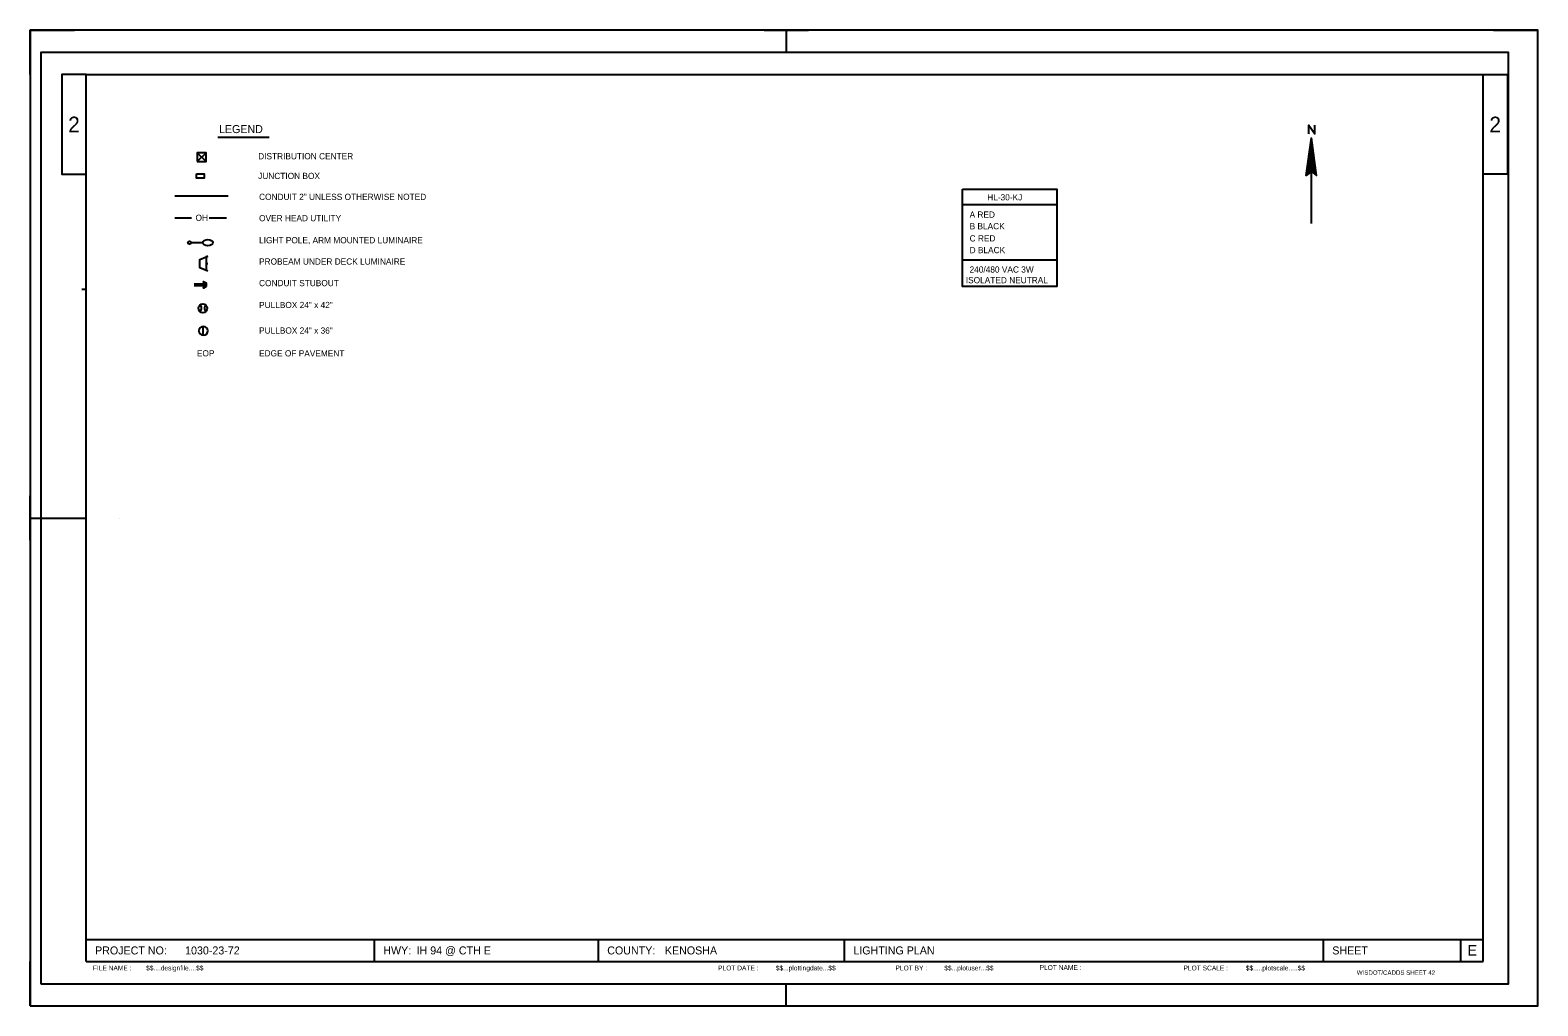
# Model space of a CAD drawing. Extents: x 589059 to 596052, y 152647 to 154942.
# Drawn here: x 589059 to 590759, y 152647 to 153747 of the extents above; entities that cross this region are included whole.
import ezdxf

# ---------------------------------------------------------------- set-up
doc = ezdxf.new("R2010")
doc.units = 0
for name, color, linetype in [('b_center line', 7, 'Continuous'), ('Level 26', 7, 'Continuous'), ('Level 28', 7, 'Continuous'), ('P_DRN_Flow', 7, 'Continuous'), ('P_DRN_SS_UG', 7, 'Continuous')]:
    doc.layers.add(name, color=color, linetype=linetype)

msp = doc.modelspace()

# ---------------------------------------------------------------- linework, layer by layer
at = {"layer": 'b_center line'}
msp.add_line((589270.3, 153625.9), (589328.2, 153625.9), dxfattribs=at)
at = {"layer": 'Level 26'}
for p, q in [((589247, 153608.5), (589257, 153598.5)), ((589247, 153598.5), (589257, 153608.5)), ((590109.8, 153550.2), (590216.2, 153550.2)), ((589240.1, 153507.1), (589253.4, 153507.1)), ((589250.1, 153488.1), (589259.1, 153491.7)), ((589250.1, 153478.5), (589250.1, 153488.1)), ((589259.1, 153475), (589250.1, 153478.5)), ((589257, 153490.9), (589257, 153490.9)), ((589259.1, 153491.7), (589257.1, 153490.9)), ((589257.1, 153490.9), (589257.1, 153475.8)), ((589257.1, 153483.4), (589259.1, 153483.4)), ((590109.8, 153487.7), (590216.2, 153487.7)), ((589253.9, 153402.6), (589253.9, 153412.6)), ((589253.7, 153402.6), (589253.9, 153402.6))]:
    msp.add_line(p, q, dxfattribs=at)
for points in [[(589247, 153598.5), (589257, 153598.5), (589257, 153608.5), (589247, 153608.5)], [(589246.4, 153584.5), (589254.9, 153584.5), (589254.9, 153579.6), (589246.4, 153579.6)], [(590109.8, 153567.2), (590216.2, 153567.2), (590216.2, 153457.5), (590109.8, 153457.5)], [(589257.3, 153457.6), (589254.2, 153455.9), (589255.5, 153459.6), (589254.2, 153463.4), (589257.3, 153461.6)]]:
    msp.add_lwpolyline(points, close=True, dxfattribs=at)
for points in [[(589281.9, 153559.5), (589221.7, 153559.5)], [(589259.1, 153475), (589250.1, 153478.5), (589250.1, 153488.1), (589257.1, 153490.9), (589257.1, 153475.8)], [(589243.5, 153460.6), (589257.3, 153460.6)], [(589243.5, 153458.6), (589257.3, 153458.6)]]:
    msp.add_lwpolyline(points, dxfattribs=at)
for centre, radius in [((589238.4, 153507.1), 1.76), ((589253.4, 153433.1), 5)]:
    msp.add_circle(centre, radius, dxfattribs=at)
for centre, start, end in [((589246.9, 153433.4), 308.3742, 47.6044), ((589260.2, 153433.3), 134.4184, 228.4474), ((589253.9, 153407.6), 91.3904, 267.7675), ((589253.9, 153407.6), 270, 90), ((589253.9, 153407.6), 90, 90.0855), ((589253.9, 153407.6), 269.4927, 270)]:
    msp.add_arc(centre, 5, start, end, dxfattribs=at)
msp.add_ellipse((589259, 153507.1), major_axis=(5.6, 0), ratio=0.621156, dxfattribs=at)
at = {"layer": 'Level 28'}
for p, q in [((589221.7, 153535.1), (589240.6, 153535.1)), ((589260.6, 153535.1), (589279.9, 153535.1))]:
    msp.add_line(p, q, dxfattribs=at)
at = {"layer": 'P_DRN_Flow'}
for p, q in [((589058.7, 153696.6), (589058.7, 153746.6)), ((589058.7, 153746.6), (589108.7, 153746.6)), ((589886.2, 153746.6), (589936.2, 153746.6)), ((589911.2, 153746.6), (589911.2, 153721.6)), ((590708.7, 153746.6), (590758.7, 153746.6)), ((590758.7, 153696.6), (590758.7, 153746.6)), ((589121.9, 153696.6), (590696.9, 153696.6)), ((589121.9, 152696.6), (589121.9, 153696.6)), ((590696.9, 152696.6), (590696.9, 153696.6)), ((590500.7, 153639.3), (590500.7, 153639.3)), ((590500.7, 153629.4), (590500.7, 153629.4)), ((590503.4, 153625.3), (590503.2, 153624.9)), ((590503.4, 153625.3), (590503.4, 153625.3)), ((590503.4, 153625.3), (590503.4, 153625.3)), ((590503.4, 153625.3), (590503.4, 153625.3)), ((590503.4, 153625.3), (590503.4, 153625.3)), ((590497.6, 153582.8), (590497.6, 153582.8)), ((590497.9, 153583.3), (590497.9, 153583.3)), ((590498.7, 153591.3), (590498.7, 153591.3)), ((590499, 153591.7), (590499, 153591.7)), ((590503.4, 153528.5), (590503.4, 153587.2)), ((590503.4, 153528.5), (590503.4, 153587.2)), ((590507.7, 153591.7), (590507.7, 153591.7)), ((590508, 153591.3), (590508, 153591.3)), ((590508.8, 153583.3), (590508.8, 153583.3)), ((590509.1, 153582.8), (590509.1, 153582.8)), ((589121.9, 153454.1), (589116.9, 153454.1)), ((589058.7, 153171.6), (589058.7, 153221.6)), ((589058.7, 153196.6), (589121.9, 153196.6)), ((589159.4, 153196.6), (589159.4, 153196.6)), ((589121.9, 152721.6), (590696.9, 152721.6)), ((589446.9, 152696.6), (589446.9, 152721.6)), ((589699.4, 152696.6), (589699.4, 152721.6)), ((589976.9, 152696.6), (589976.9, 152721.6)), ((590516.9, 152696.6), (590516.9, 152721.6)), ((590671.9, 152696.6), (590671.9, 152721.6)), ((589058.7, 152646.6), (589058.7, 152696.6)), ((589121.9, 152696.6), (590696.9, 152696.6)), ((590758.7, 152646.6), (590758.7, 152696.6)), ((589911.2, 152646.6), (589911.2, 152671.6)), ((589058.7, 152646.6), (589108.7, 152646.6)), ((589886.2, 152646.6), (589936.2, 152646.6)), ((590708.7, 152646.6), (590758.7, 152646.6))]:
    msp.add_line(p, q, dxfattribs=at)
for points in [[(589121.9, 153696.6), (589094.4, 153696.6), (589094.4, 153584.1), (589121.9, 153584.1)], [(590696.9, 153696.6), (590724.4, 153696.6), (590724.4, 153584.1), (590696.9, 153584.1)]]:
    msp.add_lwpolyline(points, close=True, dxfattribs=at)
for points in [[(590500.6, 153629.7), (590500.6, 153639.5), (590507.1, 153629.7), (590507.1, 153639.5)], [(590503.4, 153587.2), (590497.6, 153582.8), (590503.4, 153625.3)], [(590498.4, 153584.2), (590503.4, 153622.4), (590499.3, 153584.8), (590500.2, 153585.6), (590503.3, 153618.6), (590501, 153586.3), (590501.8, 153587.1), (590503.3, 153613.9), (590502.8, 153587.6)], [(590503.4, 153587.2), (590509.1, 153582.8), (590503.4, 153625.3)], [(590508.5, 153584.2), (590503.5, 153622.4), (590507.6, 153584.8), (590506.7, 153585.6), (590503.6, 153618.6), (590505.9, 153586.3), (590505, 153587.1), (590503.6, 153613.9), (590504, 153587.6)]]:
    msp.add_lwpolyline(points, dxfattribs=at)
at = {"layer": 'P_DRN_SS_UG'}
for points in [[(589058.7, 152646.6), (590758.7, 152646.6), (590758.7, 153746.6), (589058.7, 153746.6)], [(589070.7, 152671.6), (590725.7, 152671.6), (590725.7, 153721.6), (589070.7, 153721.6)]]:
    msp.add_lwpolyline(points, close=True, dxfattribs=at)

# ---------------------------------------------------------------- texts
at = {"layer": 'b_center line'}
for s, height, p in [('LEGEND', 9, (589271.6, 153630.6)), ('DISTRIBUTION CENTER', 7, (589315.8, 153601)), ('JUNCTION BOX', 7, (589315.8, 153578.8)), ('CONDUIT 2" UNLESS OTHERWISE NOTED', 7, (589316.8, 153555.2)), ('HL-30-KJ', 7, (590137.8, 153554.7)), ('OVER HEAD UTILITY', 7, (589316.8, 153531.2)), ('A RED', 7, (590118, 153535.2)), ('B BLACK', 7, (590118, 153522.1)), ('LIGHT POLE, ARM MOUNTED LUMINAIRE', 7, (589316.8, 153506.3)), ('C RED', 7, (590118, 153508.4)), ('D BLACK', 7, (590118, 153495.2)), ('PROBEAM UNDER DECK LUMINAIRE', 7, (589316.8, 153482.3)), ('240/480 VAC 3W', 7, (590117.9, 153473.3)), ('CONDUIT STUBOUT', 7, (589316.8, 153458)), ('ISOLATED NEUTRAL', 7, (590113.7, 153461.3)), ('PULLBOX 24" x 42"', 7, (589316.8, 153433.3)), ('PULLBOX 24" x 36"', 7, (589316.8, 153404.5)), ('EOP', 7, (589246.7, 153378.8)), ('EDGE OF PAVEMENT', 7, (589316.8, 153378.8))]:
    msp.add_text(s, height=height, dxfattribs=at).set_placement(p)
at = {"layer": 'Level 28'}
msp.add_text('OH', height=7, rotation=359.9568, dxfattribs=at).set_placement((589245.2, 153531.6))
at = {"layer": 'P_DRN_Flow'}
for s, height, p in [('2', 17.5, (589101.6, 153631.6)), ('2', 17.5, (590704.1, 153631.6)), ('PROJECT NO:', 9, (589131.9, 152704.6)), ('1030-23-72             ', 9, (589233.4, 152704.6)), ('HWY:', 9, (589456.9, 152704.6)), ('IH 94 @ CTH E       ', 9, (589494.4, 152704.6)), ('COUNTY:', 9, (589709.4, 152704.6)), ('KENOSHA             ', 9, (589774.4, 152704.6)), ('LIGHTING PLAN                                     ', 9, (589986.9, 152704.6)), ('SHEET ', 9, (590526.9, 152704.6)), ('E', 12, (590679.5, 152703.2)), ('FILE NAME :', 5.4, (589129.4, 152686.6)), ('PLOT NAME :                      ', 5.4, (590196.9, 152687.1)), ('PLOT SCALE : ', 5.4, (590359.2, 152686.6)), ('$$.....plotscale.....$$', 5.4, (590429.4, 152686.6)), ('WISDOT/CADDS SHEET 42', 5, (590554.6, 152681.6))]:
    msp.add_text(s, height=height, dxfattribs=at).set_placement(p)
for s, p in [('$$....designfile....$$', (589189.4, 152686.6)), ('PLOT DATE :', (589834.4, 152686.6)), ('$$...plottingdate...$$', (589899.4, 152686.6)), ('PLOT BY :', (590034.4, 152686.6)), ('$$...plotuser...$$', (590089.4, 152686.6))]:
    msp.add_text(s, height=5.4, rotation=360, dxfattribs=at).set_placement(p)

doc.saveas('drawing.dxf')
